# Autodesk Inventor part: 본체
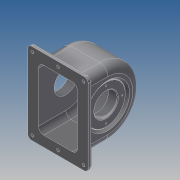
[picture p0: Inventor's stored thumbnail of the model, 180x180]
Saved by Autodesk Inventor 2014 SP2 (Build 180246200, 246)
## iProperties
Created: 2015-09
Part Number: 본체
Material: 일반
Document SubType Name: Modeling
Designer: 201-17
Density: 1 g/cm^3
Appearance: 기본값
Author: 201-17
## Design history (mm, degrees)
sketch "스케치1"
  geometry: L1 (-38.5, 0)-(38.5, 0); L2 (38.5, 0)-(38.5, 43); L3 (24.5, 57)-(-24.5, 57); L4 (-38.5, 43)-(-38.5, 0); L5 (-24.5, 52)-(24.5, 52); L6 (33.5, 43)-(33.5, 0); L7 (-33.5, 0)-(-33.5, 43); A1 r 14 centre (-24.5, 43) between (-24.5, 57) and (-38.5, 43); A2 r 14 centre (24.5, 43) between (38.5, 43) and (24.5, 57); A3 r 9 centre (24.5, 43) between (33.5, 43) and (24.5, 52); A4 r 9 centre (-24.5, 43) between (-24.5, 52) and (-33.5, 43); 3 further points
  constraints: 14 end point, 8 point on circle, 6 point on line, 4 centre point, 4 tangent, 3 parallel, 1 equal radius, 1 horizontal, 1 perpendicular, 1 other
  dimensions: "d0" = 77 distance of point (38.5, 57) point (-38.5, 57); "d1" = 57 distance of point (-38.5, 57) L1.start; "d2" = 0 vertical distance of L1.start point (0, 0); "d3" = 38.5 distance of L1.start point (0, 0) (= 0.5 x d0); "d4" = 14 radius of A1; "d5" = 5 distance between parallel lines of L5 L3; "d6" = 9 radius of A4; "d7" = 43 distance of L7.start L7.end; "d8" = 43 distance of L6.start L6.end; "d9" = 33.5 distance of point (0, 0) L6.end
revolve "회전1" sketch "스케치1" stored, may be unused: angle "d10" = 180 deg
sketch "스케치2"
  geometry: L1 (58, 14)-(58, 100) reference; L2 (0, 5)-(49, 5) reference; L3 (-9, 14)-(-9, 100) reference; L4 (0, 109)-(49, 109) reference; L5 (63, 14)-(63, 100) reference; L6 (49, 114)-(0, 114) reference; L7 (-14, 14)-(-14, 100) reference; L8 (49, 0)-(0, 0) reference; A1 r 9 centre (49, 14) between (49, 5) and (58, 14) reference; A2 r 9 centre (0, 14) between (-9, 14) and (0, 5) reference; A3 r 9 centre (0, 100) between (0, 109) and (-9, 100) reference; A4 r 9 centre (49, 100) between (58, 100) and (49, 109) reference; A5 r 14 centre (49, 100) between (63, 100) and (49, 114) reference; A6 r 14 centre (0, 100) between (0, 114) and (-14, 100) reference; A7 r 14 centre (0, 14) between (-14, 14) and (0, 0) reference; A8 r 14 centre (49, 14) between (49, 0) and (63, 14) reference; 1 further point
extrude "돌출1" join sketch "스케치2" distance "d11" = 47; taper "d12" = 0 deg
sketch "스케치3"
  geometry: L1 (-27.5, 127)-(76.5, 127); L2 (76.5, 127)-(76.5, -13); L3 (76.5, -13)-(-27.5, -13); L4 (-27.5, -13)-(-27.5, 127); L5 (-27.5, 127)-(76.5, -13); L6 (76.5, 127)-(-27.5, -13); L7 (0, 0)-(49, 0) reference; L8 (63, 14)-(63, 100) reference; L9 (49, 114)-(0, 114) reference; L10 (-14, 100)-(-14, 14) reference; A1 r 14 centre (49, 14) between (49, 0) and (63, 14) reference; A2 r 14 centre (49, 100) between (63, 100) and (49, 114) reference; A3 r 14 centre (0, 100) between (0, 114) and (-14, 100) reference; A4 r 14 centre (0, 14) between (-14, 14) and (0, 0) reference; 1 further point
  constraints: 12 end point, 2 midpoint, 2 parallel, 1 horizontal, 1 perpendicular
  dimensions: "d13" = 104 distance of L2.end L3.end; "d14" = 140 distance of L1.end L2.end
extrude "돌출2" join sketch "스케치3" distance "d15" = 7; taper "d16" = 0 deg
fillet "모깎기1" dims "d17" = 7
sketch "스케치4"
  geometry: C1 r 31 at (0, 0); 1 further point
  constraints: 1 centre point, 1 coincident
  dimensions: "d18" = 62 diameter of C1
extrude "돌출3" join sketch "스케치4" distance "d19" = 10; taper "d20" = 0 deg
hole "구멍1" diameter "d23" = 40; stored, may be unused: countersink angle "d27" = 90 deg, drill point angle "d29" = 0 deg; dims "d21" = 10, "d22" = 10, "d24" = 6, "d25" = 4, "d26" = 2, "d28" = 8
node "작업 평면1"
sketch "스케치5"
  geometry: C1 r 28 at (0, 0); 1 further point
  constraints: 1 centre point, 1 coincident
  dimensions: "d31" = 56 diameter of C1
extrude "돌출4" join sketch "스케치5" stored distance "d32" = 10; taper "d33" = 40 deg
hole "구멍2" diameter "d36" = 40; stored, may be unused: countersink angle "d40" = 90 deg, drill point angle "d42" = 0 deg; dims "d37" = 6, "d38" = 4, "d39" = 2, "d41" = 16, "d54" = 10, "d55" = 10
sketch "스케치6"
  geometry: L1 (-24.5, 0)-(24.5, 0) reference; L2 (38.5, 0)-(-47.831, 0); L3 (38.5, 0)-(38.5, 43) reference; L4 (35.5, 20)-(35.5, -20) reference; L5 (35.5, 20)-(19.5, 20) reference; L6 (24.5, 0)-(33.5, 0) reference; L7 (24.5, 0)-(24.5, 0) reference; L8 (24.5, 0)-(33.5, 0) reference; L9 (33.5, 0)-(33.5, 0) reference; L10 (19.5, 28)-(33.5, 39.747) reference; L11 (34.5, 34.059)-(38.5, 37.416); L12 (35.5, 0)-(35.5, 33); L13 (35.5, 33)-(34.5, 33); L14 (38.5, 37.416)-(38.5, 0); L15 (34.5, 34.059)-(34.5, 33); L16 (35.5, 0)-(38.5, 0); 1 further point
  constraints: 14 end point, 4 parallel, 2 collinear, 2 point on line
  dimensions: "d45" = 5 distance between parallel lines of L11 L10; "d47" = 3 distance from line of L12 L3.start; "d48" = 86.33059 distance of L2.start L2.end; "d49" = 1 distance of L12.end L13.end; "d50" = 33 distance between parallel lines of L1 L13; "d51" = 0 distance from line of point (0, 0) L2; "d52" = 0 distance from line of L1 L12.start
revolve "회전2" sketch "스케치6" stored, may be unused: angle "d53" = 180 deg
sketch "스케치7"
  geometry: 2 further points
  dimensions: "d56" = 24 distance of point (0, 24) point (0, 0); "d57" = 0 horizontal distance of point (0, 0) point (0, 24)
hole "구멍3" sketch "스케치7" at (0, 24) diameter "d58" = 2.459; stored, may be unused: countersink angle "d62" = 90 deg, drill point angle "d64" = 118 deg; dims "d59" = 6, "d60" = 4, "d61" = 2, "d63" = 8
node "작업축1"
sketch "스케치8"
  geometry: 2 further points
  dimensions: "d68" = 28 distance of point (0, 0) point (0, 28); "d69" = 0 horizontal distance of point (0, 0) point (0, 28)
hole "구멍4" sketch "스케치8" at (0, 28) diameter "d70" = 2.459; stored, may be unused: countersink angle "d74" = 90 deg, drill point angle "d76" = 118 deg; dims "d71" = 7, "d72" = 4, "d73" = 2, "d75" = 9
node "작업 평면3"
  node "작업 평면2"
sketch "스케치9"
  geometry: C1 r 6 at (0, 0); 1 further point
  constraints: 1 centre point, 1 coincident
  dimensions: "d81" = 12 diameter of C1
extrude "돌출5" join sketch "스케치9" stored distance "d82" = 12; taper "d83" = 10 deg
hole "구멍5" diameter "d86" = 4.459; stored, may be unused: countersink angle "d90" = 90 deg, drill point angle "d92" = 118 deg; dims "d87" = 7, "d88" = 4, "d89" = 2, "d91" = 9, "d115" = 10, "d116" = 10
sketch "스케치10"
  geometry: L1 (76.5, -120)-(76.5, 6) reference; 4 further points
  dimensions: "d93" = 62 vertical distance of point (24.5, -57) point (-19.5, -119); "d94" = 44 distance of point (24.5, -119) point (-19.5, -119); "d95" = 44 distance of point (68.5, -119) point (24.5, -119) (= d94); "d96" = 62 vertical distance of point (24.5, -57) point (68.5, -119) (= d93); "d97" = 62 distance of point (24.5, -57) point (24.5, -119) (= d93); "d105" = 8 distance from line of point (68.5, -119) L1
hole "구멍6" sketch "스케치10" at (-19.5, -119), (24.5, -119), (68.5, -119) diameter "d98" = 5; stored, may be unused: countersink angle "d102" = 90 deg, drill point angle "d104" = 0 deg; dims "d99" = 5, "d100" = 4, "d101" = 2, "d103" = 9
sketch "스케치11"
  geometry: L1 (-20.5, -47)-(69.5, -47) reference; L2 (-14, 0)-(-14, -40) reference; 2 further points
  constraints: 1 other
  dimensions: "d106" = 30 distance from line of L1 point (24.5, -17); "d107" = 38.5 distance from line of L2 point (24.5, -17)
feature "엠보싱1" sketch "스케치11" dims "d0" = 77, "d1" = 57, "d2" = 0, "d3" = 38.5 (= 0.5 x d0), "d4" = 14, "d5" = 5, "d6" = 9, "d7" = 43, "d8" = 43, "d9" = 33.5, "d108" = 0.5, "d109" = 0
fillet "모깎기2" dims "d110" = 0.5
fillet "모깎기3" dims "d111" = 3, "d117" = 1
chamfer "모따기1" distance "d112" = 1; stored, may be unused: second distance "d113" = 2, angle "d114" = 45 deg
node "솔리드1"
pattern_circular "원형 패턴1" dims angle "d66" = 360 deg
pattern_circular "원형 패턴2" dims angle "d78" = 360 deg
mirror "대칭1"
node "투영된 루프1"
node "투영된 루프2"
other parameters: "d30" = -19, "d46" = 33, "d80" = -6
